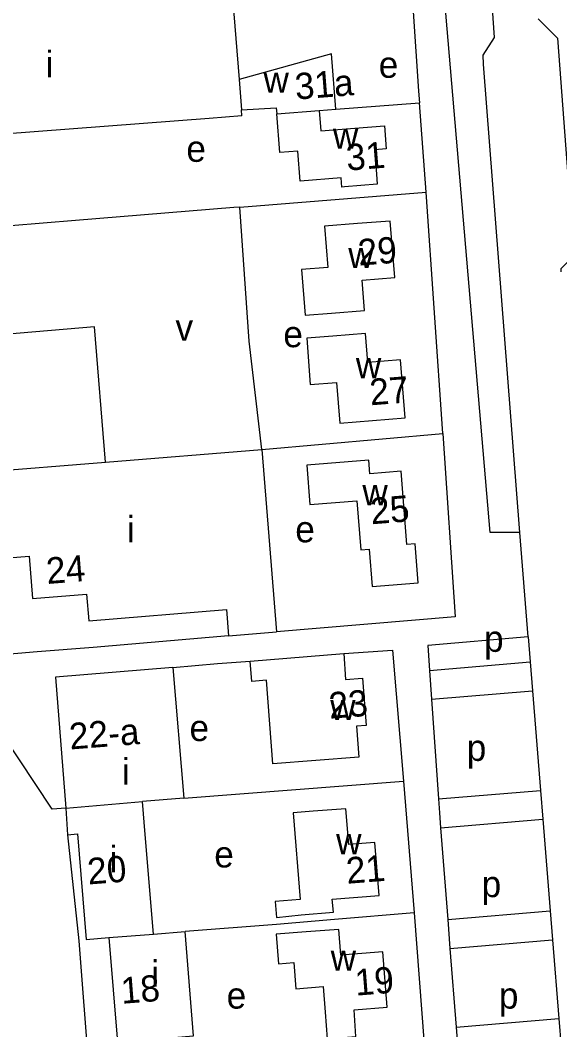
# Model space of a CAD drawing. Extents: x 157794 to 159375, y 380877 to 382306.
# Drawn here: x 158143.1 to 158225.3, y 381260.8 to 381414.5 of the extents above; entities that cross this region are included whole.
import ezdxf

# ---------------------------------------------------------------- set-up
doc = ezdxf.new("R2010")
doc.units = 0
for name, color, linetype in [('BLT_Basislijn', 7, 'Continuous'), ('BLT_Bebouwing', 7, 'Continuous'), ('BLT_Centroide', 7, 'Continuous'), ('BLT_Huisnummer', 7, 'Continuous'), ('BLT_Huisnummer_reeks', 7, 'Continuous'), ('BLT_Onderverdeling_panden', 7, 'Continuous')]:
    doc.layers.add(name, color=color, linetype=linetype)

msp = doc.modelspace()

# ---------------------------------------------------------------- linework, layer by layer
at = {"layer": 'BLT_Basislijn'}
for p, q in [((158191.15, 381400.92), (158203.9, 381401.89)), ((158204.9, 381388.28), (158203.9, 381401.89)), ((158188.62, 381400.73), (158191.15, 381400.92)), ((158176.53, 381386.02), (158204.9, 381388.28)), ((158207.46, 381351.57), (158204.9, 381388.28)), ((158179.86, 381349.14), (158207.46, 381351.57)), ((158220.44, 381320.62), (158219.17, 381336.49)), ((158174.82, 381320.78), (158154.17, 381319)), ((158220.44, 381320.62), (158220.75, 381316.79)), ((158154.17, 381319), (158145.66, 381318.3)), ((158145.66, 381318.3), (158139.71, 381317.8)), ((158166.32, 381315.95), (158173.11, 381316.53)), ((158173.11, 381316.53), (158178.1, 381316.92)), ((158205.43, 381315.5), (158220.75, 381316.79)), ((158220.75, 381316.79), (158221.1, 381312.41)), ((158205.43, 381315.5), (158205.74, 381311.11)), ((158205.74, 381311.11), (158221.1, 381312.41)), ((158205.74, 381311.11), (158206.78, 381295.92)), ((158221.1, 381312.41), (158222.32, 381297.23)), ((158167.98, 381296.06), (158201.45, 381298.62)), ((158201.45, 381298.62), (158203.06, 381278.59)), ((158206.78, 381295.92), (158222.32, 381297.23)), ((158222.32, 381297.23), (158222.67, 381292.84)), ((158207.11, 381291.53), (158222.67, 381292.84)), ((158222.67, 381292.84), (158223.79, 381278.88)), ((158207.11, 381291.53), (158208.19, 381277.56)), ((158208.19, 381277.56), (158223.79, 381278.88)), ((158223.79, 381278.88), (158224.14, 381274.49)), ((158203.06, 381278.59), (158204.63, 381258.58)), ((158208.19, 381277.56), (158208.53, 381273.17)), ((158208.53, 381273.17), (158224.14, 381274.49)), ((158224.14, 381274.49), (158225.1, 381262.52)), ((158208.53, 381273.17), (158209.46, 381261.2)), ((158209.46, 381261.2), (158225.1, 381262.52)), ((158225.1, 381262.52), (158225.45, 381258.13)), ((158209.46, 381261.2), (158209.8, 381256.81))]:
    msp.add_line(p, q, dxfattribs=at)
for points in [[(158199.22, 381438.54), (158201.07, 381433.86), (158202.1, 381427.97), (158203.77, 381403.69), (158203.9, 381401.89)], [(158219.17, 381336.49), (158214.67, 381336.49), (158207.04, 381425.67), (158206.57, 381439.69)], [(158219.17, 381336.49), (158213.66, 381407.79), (158213.61, 381409.17), (158215.34, 381411.84), (158214.09, 381429.48)], [(158221.95, 381414.68), (158224.91, 381411.72), (158227.38, 381378.6), (158225.41, 381376.62), (158225.44, 381376.15)], [(158176.53, 381386.02), (158175.62, 381385.95), (158151.51, 381383.98), (158141.66, 381383.18)], [(158179.86, 381349.14), (158177.98, 381365.63), (158176.53, 381386.02)], [(158207.46, 381351.57), (158209.34, 381323.65), (158182.12, 381321.38)], [(158220.44, 381320.62), (158205.17, 381319.28), (158205.43, 381315.5)], [(158150.01, 381294.53), (158147.94, 381294.35), (158132.79, 381317.23)], [(158192.35, 381318.05), (158199.8, 381318.56), (158201.45, 381298.62)], [(158206.78, 381295.92), (158206.93, 381293.82), (158207.11, 381291.53)], [(158150.31, 381290.48), (158152, 381274.32), (158153.56, 381254.59)], [(158203.06, 381278.59), (158190.95, 381277.58), (158182.1, 381276.8), (158168.19, 381275.76)]]:
    msp.add_lwpolyline(points, dxfattribs=at)
at = {"layer": 'BLT_Bebouwing'}
for p, q in [((158175.3, 381419.31), (158176.41, 381405.43)), ((158176.41, 381405.43), (158176.78, 381400.81)), ((158176.85, 381399.89), (158176.78, 381400.81)), ((158156.07, 381347.21), (158179.86, 381349.14)), ((158144.43, 381332.9), (158144.95, 381326.46)), ((158144.95, 381326.46), (158153.18, 381327.12)), ((158153.18, 381327.12), (158153.51, 381323.06)), ((158174.82, 381320.78), (158182.12, 381321.38)), ((158178.1, 381316.92), (158192.35, 381318.05)), ((158166.32, 381315.95), (158167.98, 381296.06)), ((158167.98, 381296.06), (158161.69, 381295.52)), ((158150.01, 381294.53), (158150.31, 381290.48)), ((158163.36, 381275.36), (158168.19, 381275.76))]:
    msp.add_line(p, q, dxfattribs=at)
for points in [[(158191.15, 381400.92), (158190.49, 381409.33), (158176.41, 381405.43)], [(158176.78, 381400.81), (158182.07, 381401.15), (158182.15, 381400.2)], [(158188.62, 381400.73), (158188.86, 381397.64), (158198.58, 381398.4), (158198.84, 381394.89), (158197.1, 381394.74), (158197.47, 381389.51), (158192.49, 381389.1), (158192.09, 381389.07), (158191.97, 381390.47), (158185.73, 381389.96), (158185.35, 381394.54), (158182.63, 381394.32), (158182.15, 381400.2)], [(158176.85, 381399.89), (158171.86, 381399.51), (158140.55, 381397.1)], [(158194.47, 381383.5), (158189.42, 381383.1), (158189.92, 381376.82), (158185.95, 381376.5), (158186.5, 381369.57), (158190.52, 381369.89), (158195.5, 381370.28), (158195.14, 381374.88), (158200.13, 381375.28), (158199.45, 381383.89), (158194.47, 381383.5)], [(158156.07, 381347.21), (158154.4, 381367.78), (158124.55, 381365.28), (158119.48, 381364.94)], [(158196.72, 381353.54), (158201.7, 381353.93), (158201, 381362.77), (158196.02, 381362.38), (158195.67, 381366.77), (158190.68, 381366.38), (158186.72, 381366.07), (158187.27, 381359.02), (158191.25, 381359.33), (158191.74, 381353.15), (158196.72, 381353.54)], [(158179.86, 381349.14), (158182.12, 381321.38)], [(158201.96, 381334.64), (158201.08, 381345.8), (158196.33, 381345.42), (158196.17, 381347.5), (158186.72, 381346.75), (158187.19, 381340.76), (158194.34, 381341.33), (158194.94, 381333.83), (158196.25, 381333.93)], [(158137.07, 381345.67), (158138.15, 381332.39), (158144.43, 381332.9)], [(158196.25, 381333.93), (158196.7, 381328.27), (158203.69, 381328.82), (158203.22, 381334.74), (158201.96, 381334.64)], [(158153.51, 381323.06), (158174.5, 381324.77), (158174.82, 381320.78)], [(158192.35, 381318.05), (158192.65, 381314.11), (158195.22, 381314.31), (158195.78, 381307.1), (158194.28, 381306.99), (158194.65, 381302.28), (158181.58, 381301.26), (158180.58, 381314.01), (158178.34, 381313.83), (158178.1, 381316.92)], [(158166.32, 381315.95), (158148.48, 381314.44), (158150.01, 381294.53)], [(158163.36, 381275.36), (158162.1, 381290.54), (158161.69, 381295.52)], [(158190.62, 381280.68), (158197.73, 381281.23), (158197.1, 381289.28), (158193.11, 381288.97), (158192.68, 381294.43), (158187.7, 381294.05), (158184.67, 381293.81), (158185.7, 381280.62), (158181.92, 381280.33), (158182.11, 381277.87), (158185.89, 381278.29), (158190.78, 381278.67), (158190.62, 381280.68)], [(158150.31, 381290.48), (158151.82, 381290.6), (158153.15, 381274.55), (158156.59, 381274.84)], [(158156.59, 381274.84), (158157.91, 381258.9), (158162.9, 381259.31), (158169.5, 381259.86), (158168.19, 381275.76)], [(158193.96, 381263.82), (158198.95, 381264.21), (158198.29, 381272.67), (158191.92, 381272.17), (158191.61, 381276.08), (158186.63, 381275.69), (158182.05, 381275.34), (158182.4, 381270.84), (158184.74, 381271.02), (158185.05, 381267.03), (158189.21, 381267.36), (158189.51, 381263.47), (158189.83, 381259.42), (158194.22, 381259.76), (158193.96, 381263.82)]]:
    msp.add_lwpolyline(points, dxfattribs=at)
at = {"layer": 'BLT_Onderverdeling_panden'}
for p, q in [((158182.15, 381400.2), (158188.62, 381400.73)), ((158150.01, 381294.53), (158161.69, 381295.52)), ((158156.59, 381274.84), (158163.36, 381275.36))]:
    msp.add_line(p, q, dxfattribs=at)
msp.add_lwpolyline([(158137.07, 381345.67), (158156.07, 381347.17), (158156.07, 381347.21)], dxfattribs=at)

# ---------------------------------------------------------------- texts
at = {"layer": 'BLT_Centroide'}
for s, p in [('i', (158146.96, 381405.79)), ('e', (158197.69, 381405.7)), ('w', (158180.14, 381403.42)), ('w', (158190.71, 381394.91)), ('e', (158168.39, 381392.91)), ('w', (158193.05, 381376.73)), ('v', (158166.74, 381365.69)), ('e', (158183.16, 381364.69)), ('w', (158194.21, 381359.97)), ('w', (158195.2, 381340.64)), ('i', (158159.34, 381334.97)), ('e', (158184.98, 381334.99)), ('p', (158213.73, 381318.32)), ('w', (158190.3, 381307.94)), ('e', (158168.87, 381304.74)), ('p', (158211.09, 381301.72)), ('i', (158158.57, 381298.11)), ('w', (158191.2, 381287.52)), ('i', (158156.7, 381284.78)), ('e', (158172.64, 381285.5)), ('p', (158213.36, 381280.98)), ('w', (158190.37, 381269.78)), ('i', (158163.05, 381267.33)), ('e', (158174.53, 381264.01)), ('p', (158215.99, 381264.01))]:
    msp.add_text(s, height=4, dxfattribs=at).set_placement(p)
at = {"layer": 'BLT_Huisnummer'}
for s, rotation, p in [('31a', 4.4709, (158185.07, 381402.37)), ('31', 4.4709, (158192.87, 381391.56)), ('29', 4.4709, (158194.66, 381377.1)), ('27', 4.4709, (158196.44, 381355.84)), ('25', 4.4709, (158196.56, 381337.73)), ('24', 4.4729, (158147.19, 381328.64)), ('23', 4.4709, (158190.23, 381308.13)), ('20', 4.4729, (158153.46, 381282.9)), ('21', 4.4709, (158192.87, 381283.01)), ('19', 4.4709, (158194.2, 381265.98)), ('18', 4.4729, (158158.56, 381264.74))]:
    msp.add_text(s, height=4, rotation=rotation, dxfattribs=at).set_placement(p)
at = {"layer": 'BLT_Huisnummer_reeks'}
msp.add_text('22-a', height=4, rotation=4.4729, dxfattribs=at).set_placement((158150.69, 381303.45))

doc.saveas('drawing.dxf')
